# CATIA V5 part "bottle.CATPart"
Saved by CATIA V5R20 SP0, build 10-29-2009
Part number: bottle
Bounding box of the stored display mesh (mm): x -25 to 25, y -25 to 35, z 0 to 100
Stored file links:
  D:\QQ\2382019442\FileRecv\bottle.CATPart
  D:\CATIA V5 R20 WIN64\CATIA V5 R20\win_b64\startup\materials\Catalog.CATMaterial
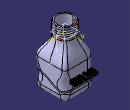
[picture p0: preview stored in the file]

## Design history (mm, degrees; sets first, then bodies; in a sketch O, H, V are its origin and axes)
Set1
  Sketch1 on xy-plane, origin (0, 0, 0), H (1, 0, 0), V (0, 1, 0)
    line L1 (25, 25) -> (25, -25)
    line L2 (25, -25) -> (-25, -25)
    line L3 (-25, -25) -> (-25, 25)
    line L4 (-25, 25) -> (25, 25)
    length L1 = 50
    length L4 = 50
    vertical: L1 V, L3 V
    horizontal: L2 H, L4 H
    equidistance: L1 L3 O, L2 L4 O
  Sketch2 on face of Pad1 from Sketch1.L1, origin (25, 0, 0), H (0, 1, 0), V (0, 0, 1)
    spline S1 through (-38.9108, 19.6143) (-8.9108, 29.6143) (11.0892, 19.6143) (41.0892, 29.6143)
  Extrude1: Element1 Sketch2, Lim1 63, Lim2 63
  MultiSel1: CommonCtxFeats ({extract ExtractElem face of Pad1 from Sketch1.L4}; {extract ExtractElem face of Fillet1}; {extract ExtractElem face of Pad1 from Sketch1.L1}; {extract ExtractElem face of Fillet1}; {extract ExtractElem face of Pad1 from Sketch1.L3}; {extract ExtractElem face of Pad1 from Sketch1.L2}; {extract ExtractElem face of Fillet1}; {extract ExtractElem face of Fillet1})
  Join1: Elements ({intersect ToIntersect1 {extract ExtractElem face of Pad1 from Sketch1.L4}, ToIntersect2 Extrude1}; {intersect ToIntersect1 {extract ExtractElem face of Fillet1}, ToIntersect2 Extrude1}; {intersect ToIntersect1 {extract ExtractElem face of Pad1 from Sketch1.L1}, ToIntersect2 Extrude1}; {intersect ToIntersect1 {extract ExtractElem face of Fillet1}, ToIntersect2 Extrude1}; {intersect ToIntersect1 {extract ExtractElem face of Pad1 from Sketch1.L3}, ToIntersect2 Extrude1}; {intersect ToIntersect1 {extract ExtractElem face of Pad1 from Sketch1.L2}, ToIntersect2 Extrude1}; {intersect ToIntersect1 {extract ExtractElem face of Fillet1}, ToIntersect2 Extrude1}; {intersect ToIntersect1 {extract ExtractElem face of Fillet1}, ToIntersect2 Extrude1})
  Plane1: type Normal, Curve Join1, RefPoint vertex [face of MultiSel1 | face of MultiSel1]
  Sketch3 on Plane1, origin (0, -18.6105, 3.3142), H (-1, 0, 0), V (0, 0.1753, 0.9845)
    circle A1 centre (-24.9056, 28.2455) radius 1
    radius A1 = 1
Body1 (main body)
  Pad1: profile Sketch1, direction (0, 0, 1), length 50
  Fillet1: on edge [face of Pad1 from Sketch1.L1 | face of Pad1 from Sketch1.L2]; edge [face of Pad1 from Sketch1.L4 | face of Pad1 from Sketch1.L1]; edge [face of Pad1 from Sketch1.L2 | face of Pad1 from Sketch1.L3]; edge [face of Pad1 from Sketch1.L3 | face of Pad1 from Sketch1.L4]
  Fillet2: on edge [start face of Pad1 | face of Pad1 from Sketch1.L1]
  Plane2: type Offset, RefPlane end face of Pad1, Offset 50, reversed
  Sketch4 on Plane2, origin (0, 0, 100), H (1, 0, 0), V (0, -1, 0)
    circle A1 centre (0, 0) radius 15
    radius A1 = 15
  Pad2: profile Sketch4, direction (0, 0, -1), length 20
  Sketch5 on end face of Pad1, origin (0, 0, 50), H (1, 0, 0), V (0, 1, 0)
    point P1 (25, 0)
    distance P1 O = 25
    coincidence: P1 H
  Sketch6 on end face of Pad2, origin (0, 0, 80), H (1, 0, 0), V (0, -1, 0)
    point P1 (15, 0)
    distance P1 O = 15
    coincidence: P1 H
  Loft1: solid, Sections ({boundary Boundary {extract ExtractElem end face of Pad2}}; {boundary Boundary {extract ExtractElem end face of Pad1}}), StartFace end face of Pad2, EndFace end face of Pad1
  Slot1: profile Sketch3, centre curve Join1
  Shell1: IntOffset 2, Face start face of Pad2, ExtOffset 0
  Sketch7 on face of Pad1 from Sketch1.L2, origin (0, -25, 0), H (1, 0, 0), V (0, 0, 1)
    spline S1 through (-34.2301, 36.4407) (-15.2364, 45.0029) (4.7483, 37.5933) (36.2944, 50.766)
Body2
  Sketch8 on face of Pad1 from Sketch1.L4, origin (0, 25, 0), H (-1, 0, 0), V (0, 0, 1)
    polyline C1
    polyline C2
    polyline C3
    polyline C4
    polyline C5
    polyline C6
    polyline C7
    polyline C8
    polyline C9
    polyline C10
    polyline C11
  Pad3: profile Sketch8, direction (0, 1, 0), length 10
  Plane3: type Offset, RefPlane xy-plane, Offset 83
  Sketch9 on Plane3, origin (0, 0, 83), H (1, 0, 0), V (0, 1, 0)
    point P1 (15, 0)
    distance P1 O = 15
    coincidence: P1 H
  Sketch10 on Plane3, origin (0, 0, 83), H (1, 0, 0), V (0, 1, 0)
    point P1 (15, 1.1094)
    distance P1 V = 15
  Helix1: Direction Z axis, RefPoint Sketch10, Pitch 3, Height 16, TaperAngle 0
  Line1: type PtDir, RefPoint vertex of Helix1, Direction (0, 1, 0), Start 0, End 5
  Line2: type PtDir, RefPoint Sketch10, Direction (1, 0, 0), Start 0, End 5
  Point1: type OnCurve, Support Helix1, Length 5
  Point2: type OnCurve, Support Helix1, Length 5, RefPoint vertex of Helix1
  Connect1: Curve1 Line1, Point1 vertex of Line1, Tension1 1, Curve2 Helix1, Point2 Point2, Tension2 1
  Connect2: Curve1 Line2, Point1 vertex of Line2, Tension1 1, Curve2 Connect1, Point2 Point1, Tension2 1
  Plane4: type Normal, Curve Connect2, RefPoint Point1
  Circle1: type CtrRad, Start 0, End 180, Radius 1, Center Point1, Support Plane4, FirstDirection (-0.9187, -0.395, 0)
  Rib1: profile Circle1, centre curve Connect2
